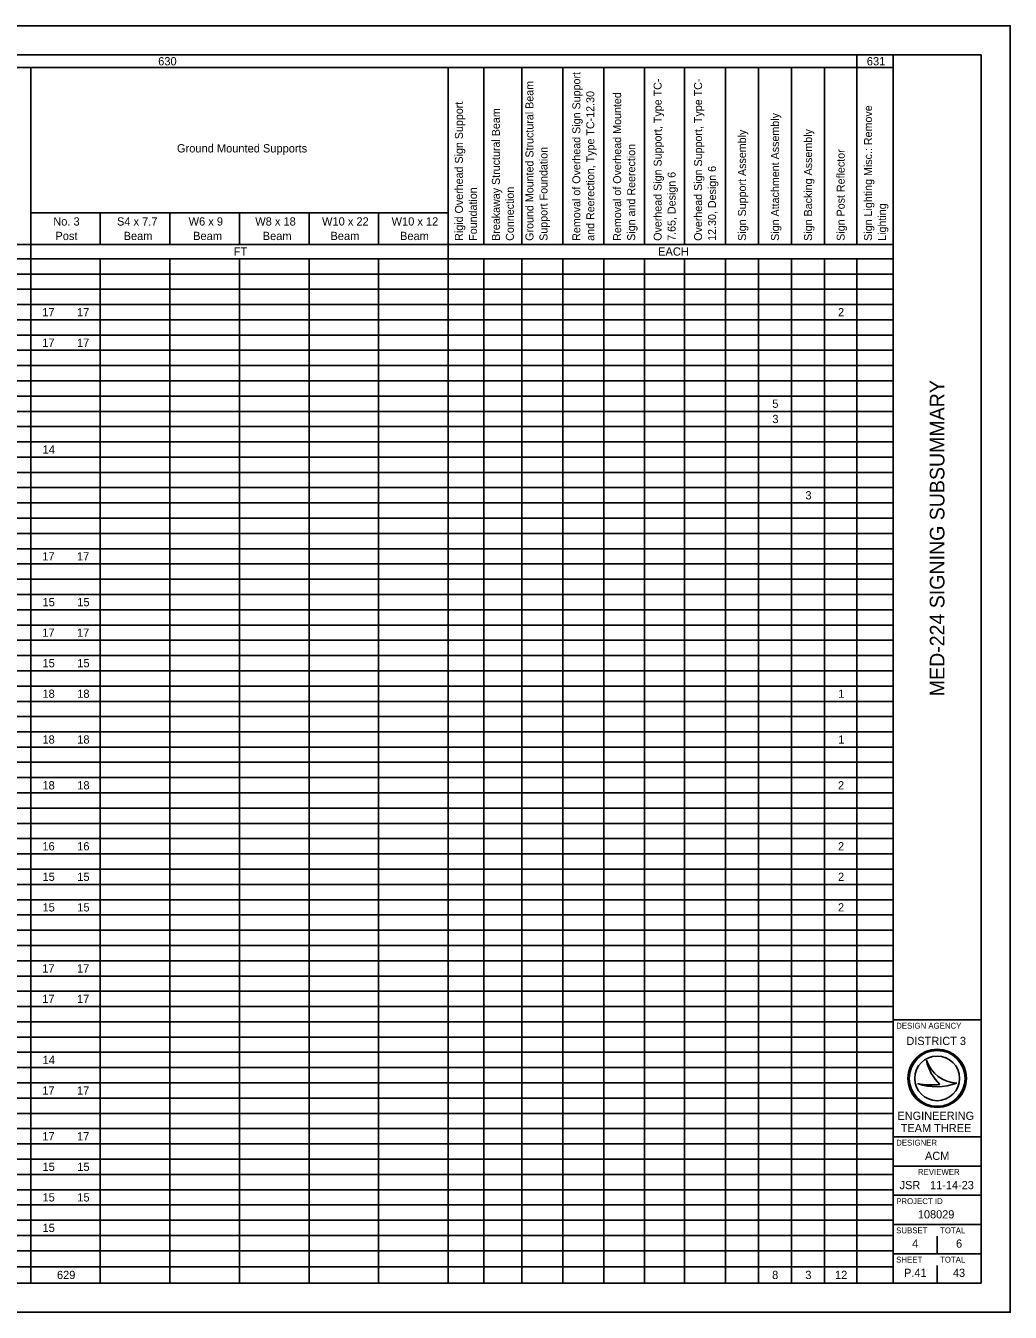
# Model space of a CAD drawing. Extents: x 0 to 34, y 0 to 22.
# Drawn here: x 17.17 to 34, y 0 to 22 of the extents above; entities that cross this region are included whole.
import ezdxf

# ---------------------------------------------------------------- set-up
doc = ezdxf.new("R2010")
doc.units = 0
for name, color, linetype in [('SH_Border', 7, 'Continuous'), ('SH_Cut_Line', 7, 'Continuous'), ('SH_Data', 7, 'Continuous'), ('SH_Text', 7, 'Continuous')]:
    doc.layers.add(name, color=color, linetype=linetype)

msp = doc.modelspace()

# ---------------------------------------------------------------- linework, layer by layer
at = {"layer": 'SH_Border'}
for p, q in [((32, 0.5), (32, 21.5)), ((32, 5), (33.5, 5)), ((32, 3), (33.5, 3)), ((32, 2.5), (33.5, 2.5)), ((32, 2), (33.5, 2)), ((32, 1.5), (33.5, 1.5)), ((32, 1), (33.5, 1))]:
    msp.add_line(p, q, dxfattribs=at)
msp.add_lwpolyline([(1.5, 21.5), (33.5, 21.5), (33.5, 0.5), (1.5, 0.5)], close=True, dxfattribs=at)
at = {"layer": 'SH_Cut_Line'}
msp.add_lwpolyline([(0, 0), (34, 0), (34, 22), (0, 22)], close=True, dxfattribs=at)
at = {"layer": 'SH_Data'}
for p, q in [((32.567, 4.31), (32.567, 4.31)), ((32.75, 4), (32.75, 4)), ((32.417, 3.91), (32.417, 3.91)), ((33.087, 3.919), (33.087, 3.919)), ((32.75, 1), (32.75, 1.3)), ((32.375, 0.675), (32.375, 0.675)), ((32.75, 0.5), (32.75, 0.8))]:
    msp.add_line(p, q, dxfattribs=at)
for radius in [0.5, 0.477, 0.477, 0.382]:
    msp.add_circle((32.75, 4), radius, dxfattribs=at)
for centre, radius, start, end in [((33.116, 4.498), 0.58, 198.9257, 198.9319), ((33.347, 4.47), 0.796, 191.6379, 191.6421), ((33.116, 4.498), 0.58, 198.9319, 267.1657), ((33.347, 4.47), 0.796, 191.6421, 226.0947), ((32.739, 4.87), 1.013, 251.4576, 290.0832), ((32.648, 5.154), 1.266, 259.4964, 259.4995), ((32.739, 4.87), 1.013, 251.4527, 251.4576), ((32.648, 5.154), 1.266, 259.4995, 276.6672)]:
    msp.add_arc(centre, radius, start, end, dxfattribs=at)
at = {"layer": 'SH_Text'}
for p, q in [((1.5, 21.5), (32, 21.5)), ((31.376, 21.5), (31.376, 18.261)), ((32, 21.5), (32, 18.015)), ((7.787, 21.285), (32, 21.285)), ((17.255, 21.285), (17.255, 18.015)), ((24.39, 21.285), (24.39, 18.015)), ((24.999, 21.285), (24.999, 18.261)), ((25.653, 21.285), (25.653, 18.261)), ((26.352, 21.285), (26.352, 18.261)), ((27.05, 21.285), (27.05, 18.261)), ((27.749, 21.285), (27.749, 18.261)), ((28.433, 21.285), (28.433, 18.261)), ((29.131, 21.285), (29.131, 18.261)), ((29.696, 21.285), (29.696, 18.261)), ((30.261, 21.285), (30.261, 18.261)), ((30.826, 21.285), (30.826, 18.261)), ((17.255, 18.798), (24.39, 18.798)), ((18.444, 18.798), (18.444, 18.261)), ((19.634, 18.798), (19.634, 18.261)), ((20.823, 18.798), (20.823, 18.261)), ((22.012, 18.798), (22.012, 18.261)), ((23.201, 18.798), (23.201, 18.261)), ((6.658, 18.261), (32, 18.261)), ((1.5, 18.015), (32, 18.015)), ((17.255, 18.015), (17.255, 0.5)), ((18.444, 18.015), (18.444, 0.5)), ((19.634, 18.015), (19.634, 0.5)), ((20.823, 18.015), (20.823, 0.5)), ((22.012, 18.015), (22.012, 0.5)), ((23.201, 18.015), (23.201, 0.5)), ((24.39, 18.015), (24.39, 0.5)), ((24.999, 18.015), (24.999, 0.5)), ((25.653, 18.015), (25.653, 0.5)), ((26.352, 18.015), (26.352, 0.5)), ((27.05, 18.015), (27.05, 0.5)), ((27.749, 18.015), (27.749, 0.5)), ((28.433, 18.015), (28.433, 0.5)), ((29.131, 18.015), (29.131, 0.5)), ((29.696, 18.015), (29.696, 0.5)), ((30.261, 18.015), (30.261, 0.5)), ((30.826, 18.015), (30.826, 0.5)), ((31.376, 18.015), (31.376, 0.5)), ((32, 18.015), (32, 0.5)), ((1.5, 17.754), (32, 17.754)), ((1.5, 17.493), (32, 17.493)), ((1.5, 17.232), (32, 17.232)), ((1.5, 16.971), (32, 16.971)), ((1.5, 16.711), (32, 16.711)), ((1.5, 16.45), (32, 16.45)), ((1.5, 16.189), (32, 16.189)), ((1.5, 15.928), (32, 15.928)), ((1.5, 15.667), (32, 15.667)), ((1.5, 15.406), (32, 15.406)), ((1.5, 15.145), (32, 15.145)), ((1.5, 14.884), (32, 14.884)), ((1.5, 14.623), (32, 14.623)), ((1.5, 14.362), (32, 14.362)), ((1.5, 14.101), (32, 14.101)), ((1.5, 13.84), (32, 13.84)), ((1.5, 13.579), (32, 13.579)), ((1.5, 13.318), (32, 13.318)), ((1.5, 13.057), (32, 13.057)), ((1.5, 12.796), (32, 12.796)), ((1.5, 12.535), (32, 12.535)), ((1.5, 12.274), (32, 12.274)), ((1.5, 12.013), (32, 12.013)), ((1.5, 11.752), (32, 11.752)), ((1.5, 11.491), (32, 11.491)), ((1.5, 11.23), (32, 11.23)), ((1.5, 10.969), (32, 10.969)), ((1.5, 10.708), (32, 10.708)), ((1.5, 10.447), (32, 10.447)), ((1.5, 10.186), (32, 10.186)), ((1.5, 9.925), (32, 9.925)), ((1.5, 9.664), (32, 9.664)), ((1.5, 9.404), (32, 9.404)), ((1.5, 9.143), (32, 9.143)), ((1.5, 8.882), (32, 8.882)), ((1.5, 8.621), (32, 8.621)), ((1.5, 8.36), (32, 8.36)), ((1.5, 8.099), (32, 8.099)), ((1.5, 7.838), (32, 7.838)), ((1.5, 7.577), (32, 7.577)), ((1.5, 7.316), (32, 7.316)), ((1.5, 7.055), (32, 7.055)), ((1.5, 6.794), (32, 6.794)), ((1.5, 6.533), (32, 6.533)), ((1.5, 6.272), (32, 6.272)), ((1.5, 6.011), (32, 6.011)), ((1.5, 5.75), (32, 5.75)), ((1.5, 5.489), (32, 5.489)), ((1.5, 5.228), (32, 5.228)), ((1.5, 4.967), (32, 4.967)), ((1.5, 4.706), (32, 4.706)), ((1.5, 4.445), (32, 4.445)), ((1.5, 4.184), (32, 4.184)), ((1.5, 3.923), (32, 3.923)), ((1.5, 3.662), (32, 3.662)), ((1.5, 3.401), (32, 3.401)), ((1.5, 3.14), (32, 3.14)), ((1.5, 2.879), (32, 2.879)), ((1.5, 2.618), (32, 2.618)), ((1.5, 2.357), (32, 2.357)), ((1.5, 2.096), (32, 2.096)), ((1.5, 1.836), (32, 1.836)), ((1.5, 1.575), (32, 1.575)), ((1.5, 1.314), (32, 1.314)), ((1.5, 1.053), (32, 1.053)), ((1.5, 0.776), (32, 0.776)), ((1.5, 0.5), (32, 0.5))]:
    msp.add_line(p, q, dxfattribs=at)

# ---------------------------------------------------------------- texts
at = {"layer": 'SH_Data'}
msp.add_text('MED-224 SIGNING SUBSUMMARY', height=0.25, rotation=90, dxfattribs=at).set_placement((32.875, 10.534))
for s, height, p in [('DESIGN AGENCY', 0.1, (32.05, 4.85)), ('DISTRICT 3', 0.14, (32.224, 4.57)), ('ENGINEERING', 0.14, (32.071, 3.29)), ('TEAM THREE', 0.14, (32.127, 3.08)), ('DESIGNER', 0.1, (32.05, 2.85)), ('ACM', 0.14, (32.543, 2.605)), ('REVIEWER', 0.1, (32.422, 2.35)), ('JSR', 0.14, (32.108, 2.105)), ('11-14-23', 0.14, (32.629, 2.105)), ('PROJECT ID', 0.1, (32.05, 1.85)), ('SUBSET', 0.1, (32.05, 1.35)), ('TOTAL', 0.1, (32.8, 1.35)), ('4', 0.14, (32.322, 1.105)), ('6', 0.14, (33.073, 1.105)), ('SHEET', 0.1, (32.05, 0.85)), ('TOTAL', 0.1, (32.8, 0.85)), ('P.41', 0.14, (32.184, 0.605)), ('43', 0.14, (33.02, 0.605))]:
    msp.add_text(s, height=height, dxfattribs=at).set_placement(p)
at = {"layer": 'SH_Text'}
for s, height, p in [('630', 0.1412, (19.434, 21.322)), ('631', 0.1412, (31.548, 21.322)), ('Ground Mounted Supports', 0.14123, (19.755, 19.833)), ('No. 3', 0.1412, (17.64, 18.583)), ('S4 x 7.7', 0.1412, (18.729, 18.583)), ('W6 x 9', 0.1412, (19.954, 18.583)), ('W8 x 18', 0.1412, (21.093, 18.583)), ('W10 x 22 ', 0.1412, (22.235, 18.583)), ('W10 x 12 ', 0.1412, (23.424, 18.583)), ('Post', 0.1412, (17.677, 18.335)), (' Beam', 0.1412, (18.79, 18.335)), (' Beam', 0.1412, (19.979, 18.335)), (' Beam', 0.1412, (21.168, 18.335)), ('Beam', 0.1412, (22.379, 18.335)), ('Beam', 0.1412, (23.568, 18.335)), ('FT', 0.1412, (20.723, 18.068)), ('EACH', 0.1412, (27.98, 18.068)), ('17', 0.1412, (17.452, 17.031)), ('17', 0.1412, (18.046, 17.031)), ('2', 0.141, (31.055, 17.031)), ('17', 0.1412, (17.452, 16.509)), ('17', 0.1412, (18.046, 16.509)), ('5', 0.141, (29.932, 15.466)), ('3', 0.141, (29.933, 15.205)), ('14', 0.1412, (17.458, 14.683)), ('3', 0.141, (30.498, 13.9)), ('17', 0.1412, (17.452, 12.856)), ('17', 0.1412, (18.046, 12.856)), ('15', 0.1412, (17.456, 12.073)), ('15', 0.1412, (18.051, 12.073)), ('17', 0.1412, (17.452, 11.551)), ('17', 0.1412, (18.046, 11.551)), ('15', 0.1412, (17.456, 11.029)), ('15', 0.1412, (18.051, 11.029)), ('18', 0.1412, (17.455, 10.507)), ('18', 0.1412, (18.05, 10.507)), ('1', 0.141, (31.06, 10.507)), ('18', 0.1412, (17.455, 9.724)), ('18', 0.1412, (18.05, 9.724)), ('1', 0.141, (31.06, 9.724)), ('18', 0.1412, (17.455, 8.941)), ('18', 0.1412, (18.05, 8.941)), ('2', 0.141, (31.055, 8.941)), ('16', 0.1412, (17.454, 7.898)), ('16', 0.1412, (18.049, 7.898)), ('2', 0.141, (31.055, 7.898)), ('15', 0.1412, (17.456, 7.376)), ('15', 0.1412, (18.051, 7.376)), ('2', 0.141, (31.055, 7.376)), ('15', 0.1412, (17.456, 6.854)), ('15', 0.1412, (18.051, 6.854)), ('2', 0.141, (31.055, 6.854)), ('17', 0.1412, (17.452, 5.81)), ('17', 0.1412, (18.046, 5.81)), ('17', 0.1412, (17.452, 5.288)), ('17', 0.1412, (18.046, 5.288)), ('14', 0.1412, (17.458, 4.244)), ('17', 0.1412, (17.452, 3.722)), ('17', 0.1412, (18.046, 3.722)), ('17', 0.1412, (17.452, 2.939)), ('17', 0.1412, (18.046, 2.939)), ('15', 0.1412, (17.456, 2.417)), ('15', 0.1412, (18.051, 2.417)), ('15', 0.1412, (17.456, 1.895)), ('15', 0.1412, (18.051, 1.895)), ('108029', 0.14, (32.42, 1.605)), ('15', 0.1412, (17.456, 1.373)), ('629', 0.1412, (17.703, 0.568)), ('8', 0.141, (29.929, 0.568)), ('3', 0.141, (30.496, 0.568)), ('12', 0.1412, (31.004, 0.568))]:
    msp.add_text(s, height=height, dxfattribs=at).set_placement(p)
for s, height, p in [('Removal of Overhead Sign Support ', 0.13674, (26.65, 18.322)), ('Ground Mounted Structural Beam ', 0.13674, (25.849, 18.322)), ('Overhead Sign Support, Type TC-', 0.13674, (28.04, 18.322)), ('Overhead Sign Support, Type TC-', 0.13674, (28.731, 18.322)), ('Rigid Overhead Sign Support ', 0.13674, (24.643, 18.322)), ('and Reerection, Type TC-12.30', 0.13674, (26.889, 18.322)), ('Removal of Overhead Mounted    ', 0.13674, (27.348, 18.322)), ('Breakaway Structural Beam ', 0.13674, (25.275, 18.322)), ('Sign Attachment Assembly', 0.13674, (30.047, 18.322)), ('Sign Lighting Misc.: Remove ', 0.13674, (31.637, 18.322)), ('Sign Support Assembly', 0.13674, (29.482, 18.322)), ('Sign Backing Assembly', 0.13674, (30.612, 18.322)), ('Support Foundation', 0.13674, (26.089, 18.322)), ('Sign and Reerection', 0.13674, (27.588, 18.322)), ('Sign Post Reflector', 0.13674, (31.169, 18.322)), ('12.30, Design 6', 0.13674, (28.97, 18.322)), ('7.65, Design 6', 0.13674, (28.279, 18.322)), ('Foundation', 0.1367, (24.883, 18.322)), ('Connection', 0.1367, (25.514, 18.322)), ('Lighting', 0.1367, (31.876, 18.322))]:
    msp.add_text(s, height=height, rotation=90, dxfattribs=at).set_placement(p)

doc.saveas('drawing.dxf')
